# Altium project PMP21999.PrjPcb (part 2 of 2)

## Sheet PowerStage.SchDoc
size 431 x 279 mm; Date: Not shown in title block; ApprovedBy: Not shown in title block; CheckedBy: Not shown in title block; Author: Not shown in title block; CompanyName: Not shown in title block; Engineer: Not shown in title block; Organization: Not shown in title block; Address1: Not shown in title block; Address2: Not shown in title block; Address3: Not shown in title block; Address4: Not shown in title block; DocumentNumber: 1; Revision: Use project parameter SCH_Rev; SheetNumber: 1; SheetTotal: 2; PageSetup: Record=PageOptions¦CenterHorizontal=True¦CenterVertical=True¦PrintScale=1.00¦XCorrection=1.00¦YCorrection=1.00¦PrintKind=0¦BorderSize=5000000¦LeftOffset=0¦BottomOffset=0¦Orientation=2¦PaperLength=1000¦PaperWidth=1000¦Scale=100¦PaperSource=15¦PrintQuality=600¦MediaType=1¦DitherType=10¦PaperKind=Letter¦PrintScaleMode=1
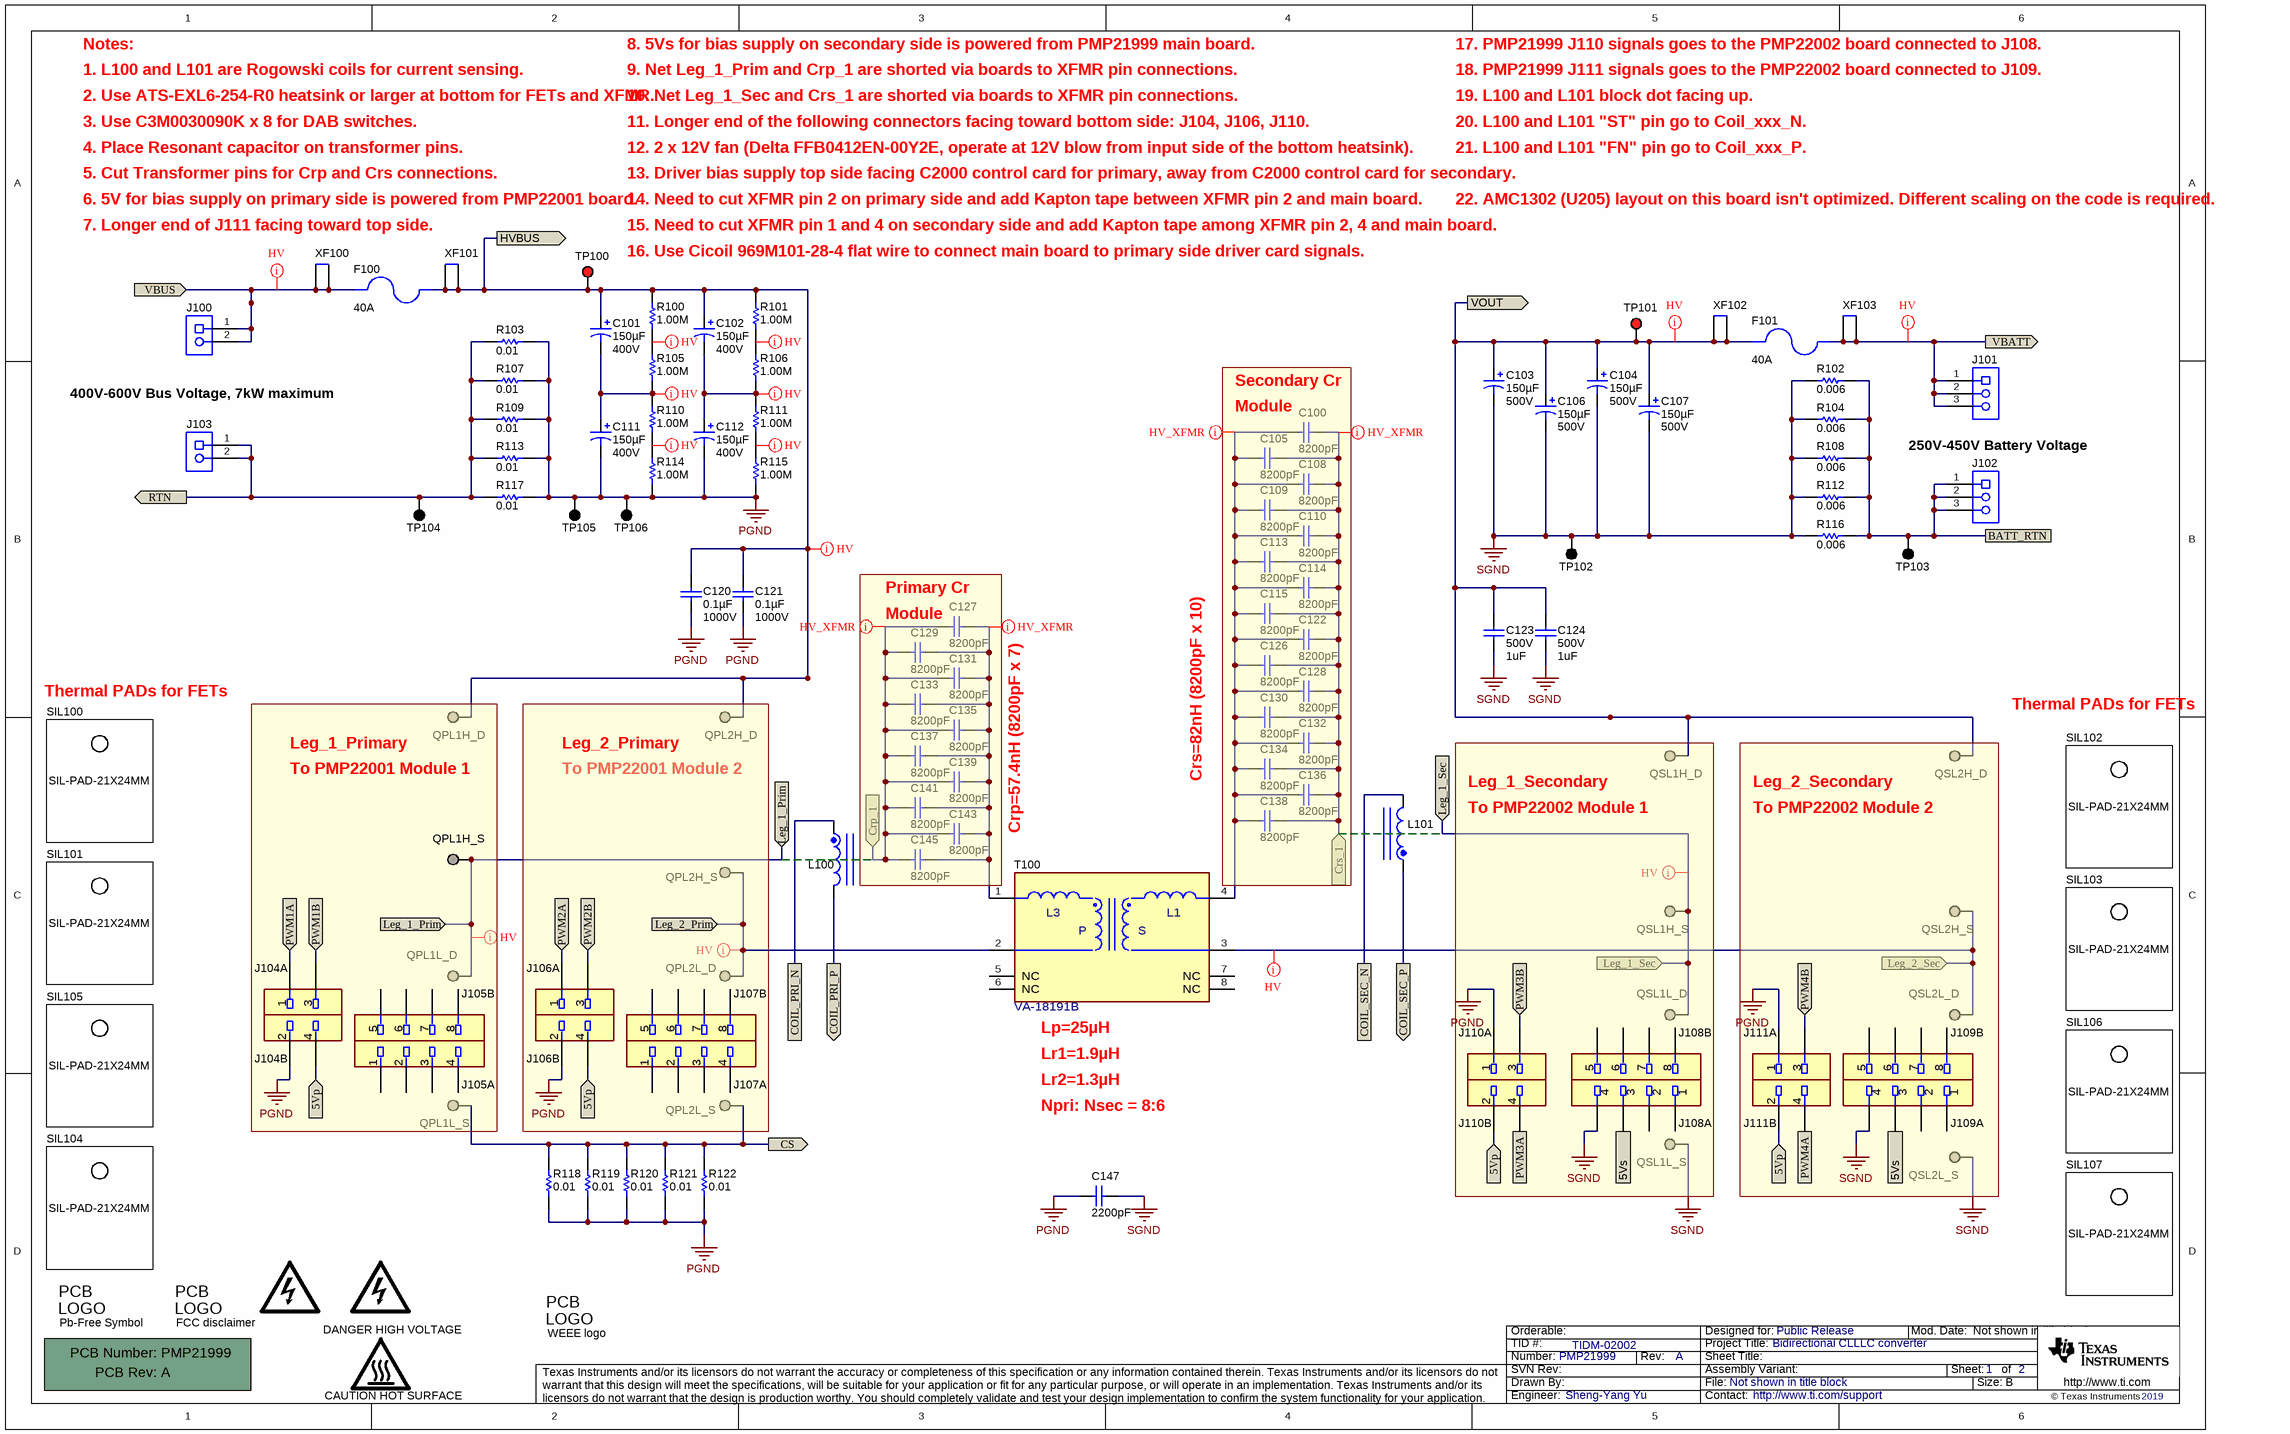
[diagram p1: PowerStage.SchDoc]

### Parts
!PCB100  Printed Circuit Board  (value not drawn)  (mechanical)
C100  ValueDisplayed: 8200pF  [1206_190]
C101  ValueDisplayed: 150µF  Value2: 400V  [FC_1600x4000]  (hidden comment: 400BXW150MEFC16X45)
C102  ValueDisplayed: 150µF  Value2: 400V  [FC_1600x4000]  (hidden comment: 400BXW150MEFC16X45)
C103  ValueDisplayed: 150µF  Value2: 500V  [Nichicon_2200x4500_Snap]  (hidden comment: 500MXG150MEFCSN22X55)
C104  ValueDisplayed: 150µF  Value2: 500V  [Nichicon_2200x4500_Snap]  (hidden comment: 500MXG150MEFCSN22X55)
C105  ValueDisplayed: 8200pF  [1206_190]
C106  ValueDisplayed: 150µF  Value2: 500V  [Nichicon_2200x4500_Snap]  (hidden comment: 500MXG150MEFCSN22X55)
C107  ValueDisplayed: 150µF  Value2: 500V  [Nichicon_2200x4500_Snap]  (hidden comment: 500MXG150MEFCSN22X55)
C108  ValueDisplayed: 8200pF  [1206_190]
C109  ValueDisplayed: 8200pF  [1206_190]
C110  ValueDisplayed: 8200pF  [1206_190]
C111  ValueDisplayed: 150µF  Value2: 400V  [FC_1600x4000]  (hidden comment: 400BXW150MEFC16X45)
C112  ValueDisplayed: 150µF  Value2: 400V  [FC_1600x4000]  (hidden comment: 400BXW150MEFC16X45)
C113  ValueDisplayed: 8200pF  [1206_190]
C114  ValueDisplayed: 8200pF  [1206_190]
C115  ValueDisplayed: 8200pF  [1206_190]
C120  ValueDisplayed: 0.1µF  Value2: 1000V  [1812_254]  (hidden comment: 1812Y1K00104KXT)
C121  ValueDisplayed: 0.1µF  Value2: 1000V  [1812_254]  (hidden comment: 1812Y1K00104KXT)
C122  ValueDisplayed: 8200pF  [1206_190]
C123  VDC_V: 500V  ValueDisplayed: 1uF  [B58031I_1084x785x450]  (hidden comment: B58031I5105M002)
C124  VDC_V: 500V  ValueDisplayed: 1uF  [B58031I_1084x785x450]  (hidden comment: B58031I5105M002)
C126  ValueDisplayed: 8200pF  [1206_190]
C127  ValueDisplayed: 8200pF  [1206_190]
C128  ValueDisplayed: 8200pF  [1206_190]
C129  ValueDisplayed: 8200pF  [1206_190]
C130  ValueDisplayed: 8200pF  [1206_190]
C131  ValueDisplayed: 8200pF  [1206_190]
C132  ValueDisplayed: 8200pF  [1206_190]
C133  ValueDisplayed: 8200pF  [1206_190]
C134  ValueDisplayed: 8200pF  [1206_190]
C135  ValueDisplayed: 8200pF  [1206_190]
C136  ValueDisplayed: 8200pF  [1206_190]
C137  ValueDisplayed: 8200pF  [1206_190]
C138  ValueDisplayed: 8200pF  [1206_190]
C139  ValueDisplayed: 8200pF  [1206_190]
C141  ValueDisplayed: 8200pF  [1206_190]
C143  ValueDisplayed: 8200pF  [1206_190]
C145  ValueDisplayed: 8200pF  [1206_190]
C147  ValueDisplayed: 2200pF  [CAPRD1000W60D900H1200]  (hidden comment: DE1E3KX222MA4BL01)
F100  Irating_A: 40A  (hidden comment: SC-40)  (mechanical)
F101  Irating_A: 40A  (hidden comment: SC-40)  (mechanical)
J100  282856-2  [TE_282856-2]  (value not drawn)
J101  282856-3  [TE_282856-3]  (value not drawn)
J102  282856-3  [TE_282856-3]  (value not drawn)
J103  282856-2  [TE_282856-2]  (value not drawn)
J104  MTMM-102-09-G-D-315  [FP-MTMM-102-09-G-D-315_HDR4-MFG]  (value not drawn)  (parts A,B of 2)
J105  MTMM-104-09-G-D-320  [FP-MTMM-104-09-G-D-320_HDR8-MFG]  (value not drawn)  (parts A,B of 2)
J106  MTMM-102-09-G-D-315  [FP-MTMM-102-09-G-D-315_HDR4-MFG]  (value not drawn)  (parts A,B of 2)
J107  MTMM-104-09-G-D-320  [FP-MTMM-104-09-G-D-320_HDR8-MFG]  (value not drawn)  (parts A,B of 2)
J108  MTMM-104-09-G-D-320  [FP-MTMM-104-09-G-D-320_HDR8-MFG]  (value not drawn)  (parts A,B of 2)
J109  MTMM-104-09-G-D-320  [FP-MTMM-104-09-G-D-320_HDR8-MFG]  (value not drawn)  (parts A,B of 2)
J110  MTMM-102-09-G-D-315  [FP-MTMM-102-09-G-D-315_HDR4-MFG]  (value not drawn)  (parts A,B of 2)
J111  MTMM-102-09-G-D-315  [FP-MTMM-102-09-G-D-315_HDR4-MFG]  (value not drawn)  (parts A,B of 2)
L100  RLTI-1310  [RLTI-1310]  (value not drawn)
L101  RLTI-1310  [RLTI-1310]  (value not drawn)
LOGO100  CAUTION HOT SURFACE  [IEC_HotSurface_Medium]  (no BOM)
Logo101  Pb-Free Symbol  [Pb-Free_Overlay_Medium]  (no BOM)
Logo102  FCC disclaimer  [FCC_disclaimer]  (no BOM)
Logo103  WEEE logo  [WEEE_Minimum]  (no BOM)
LOGO104  DANGER HIGH VOLTAGE  [IEC_HighVoltage_Medium]  (value not drawn)  (no BOM)
LOGO105  DANGER HIGH VOLTAGE  [IEC_HighVoltage_Medium]  (no BOM)
QPL1H_D  Suggest using a net name here  [Mill-Max_0312-0-15-15-34-27-10-0]  (value not drawn)
QPL1H_S  Suggest using a net name here  [Mill-Max_0312-0-15-15-34-27-10-0]  (value not drawn)
QPL1L_D  Suggest using a net name here  [Mill-Max_0312-0-15-15-34-27-10-0]  (value not drawn)
QPL1L_S  Suggest using a net name here  [Mill-Max_0312-0-15-15-34-27-10-0]  (value not drawn)
QPL2H_D  Suggest using a net name here  [Mill-Max_0312-0-15-15-34-27-10-0]  (value not drawn)
QPL2H_S  Suggest using a net name here  [Mill-Max_0312-0-15-15-34-27-10-0]  (value not drawn)
QPL2L_D  Suggest using a net name here  [Mill-Max_0312-0-15-15-34-27-10-0]  (value not drawn)
QPL2L_S  Suggest using a net name here  [Mill-Max_0312-0-15-15-34-27-10-0]  (value not drawn)
QSL1H_D  Suggest using a net name here  [Mill-Max_0312-0-15-15-34-27-10-0]  (value not drawn)
QSL1H_S  Suggest using a net name here  [Mill-Max_0312-0-15-15-34-27-10-0]  (value not drawn)
QSL1L_D  Suggest using a net name here  [Mill-Max_0312-0-15-15-34-27-10-0]  (value not drawn)
QSL1L_S  Suggest using a net name here  [Mill-Max_0312-0-15-15-34-27-10-0]  (value not drawn)
QSL2H_D  Suggest using a net name here  [Mill-Max_0312-0-15-15-34-27-10-0]  (value not drawn)
QSL2H_S  Suggest using a net name here  [Mill-Max_0312-0-15-15-34-27-10-0]  (value not drawn)
QSL2L_D  Suggest using a net name here  [Mill-Max_0312-0-15-15-34-27-10-0]  (value not drawn)
QSL2L_S  Suggest using a net name here  [Mill-Max_0312-0-15-15-34-27-10-0]  (value not drawn)
R100  ValueDisplayed: 1.00M  [1206]  (hidden comment: CRCW12061M00FKEA)
R101  ValueDisplayed: 1.00M  [1206]  (hidden comment: CRCW12061M00FKEA)
R102  ValueDisplayed: 0.006  [CSNL1206]  (hidden comment: PMR18EZPFU6L00)
R103  ValueDisplayed: 0.01  [1206]  (hidden comment: WSLP1206R0100FEA)
R104  ValueDisplayed: 0.006  [CSNL1206]  (hidden comment: PMR18EZPFU6L00)
R105  ValueDisplayed: 1.00M  [1206]  (hidden comment: CRCW12061M00FKEA)
R106  ValueDisplayed: 1.00M  [1206]  (hidden comment: CRCW12061M00FKEA)
R107  ValueDisplayed: 0.01  [1206]  (hidden comment: WSLP1206R0100FEA)
R108  ValueDisplayed: 0.006  [CSNL1206]  (hidden comment: PMR18EZPFU6L00)
R109  ValueDisplayed: 0.01  [1206]  (hidden comment: WSLP1206R0100FEA)
R110  ValueDisplayed: 1.00M  [1206]  (hidden comment: CRCW12061M00FKEA)
R111  ValueDisplayed: 1.00M  [1206]  (hidden comment: CRCW12061M00FKEA)
R112  ValueDisplayed: 0.006  [CSNL1206]  (hidden comment: PMR18EZPFU6L00)
R113  ValueDisplayed: 0.01  [1206]  (hidden comment: WSLP1206R0100FEA)
R114  ValueDisplayed: 1.00M  [1206]  (hidden comment: CRCW12061M00FKEA)
R115  ValueDisplayed: 1.00M  [1206]  (hidden comment: CRCW12061M00FKEA)
R116  ValueDisplayed: 0.006  [CSNL1206]  (hidden comment: PMR18EZPFU6L00)
R117  ValueDisplayed: 0.01  [1206]  (hidden comment: WSLP1206R0100FEA)
R118  ValueDisplayed: 0.01  [1206]  (hidden comment: WSLP1206R0100FEA)
R119  ValueDisplayed: 0.01  [1206]  (hidden comment: WSLP1206R0100FEA)
R120  ValueDisplayed: 0.01  [1206]  (hidden comment: WSLP1206R0100FEA)
R121  ValueDisplayed: 0.01  [1206]  (hidden comment: WSLP1206R0100FEA)
R122  ValueDisplayed: 0.01  [1206]  (hidden comment: WSLP1206R0100FEA)
SIL100  SP900S-0.009-00-114  [SIL-PAD_24X21MM]  (value not drawn)
SIL101  SP900S-0.009-00-114  [SIL-PAD_24X21MM]  (value not drawn)
SIL102  SP900S-0.009-00-114  [SIL-PAD_24X21MM]  (value not drawn)
SIL103  SP900S-0.009-00-114  [SIL-PAD_24X21MM]  (value not drawn)
SIL104  SP900S-0.009-00-114  [SIL-PAD_24X21MM]  (value not drawn)
SIL105  SP900S-0.009-00-114  [SIL-PAD_24X21MM]  (value not drawn)
SIL106  SP900S-0.009-00-114  [SIL-PAD_24X21MM]  (value not drawn)
SIL107  SP900S-0.009-00-114  [SIL-PAD_24X21MM]  (value not drawn)
T100  VA-18191B  [FP-VA-18191B_XFMR_PTH_8-MFG]
TP100  5000  [Keystone5000]  (value not drawn)
TP101  5000  [Keystone5000]  (value not drawn)
TP102  5001  [Keystone5001]  (value not drawn)
TP103  5001  [Keystone5001]  (value not drawn)
TP104  5001  [Keystone5001]  (value not drawn)
TP105  5001  [Keystone5001]  (value not drawn)
TP106  5001  [Keystone5001]  (value not drawn)
XF100  1A3400-10  [Eaton_1A3400-10]  (value not drawn)
XF101  1A3400-10  [Eaton_1A3400-10]  (value not drawn)
XF102  1A3400-10  [Eaton_1A3400-10]  (value not drawn)
XF103  1A3400-10  [Eaton_1A3400-10]  (value not drawn)

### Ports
5Vp (in), 5Vs (in), BATT_RTN, COIL_PRI_N, COIL_PRI_P (out), COIL_SEC_N, COIL_SEC_P (out), Crp_1 (in), Crs_1 (in), CS (out), HVBUS (out), Leg_1_Prim (in), Leg_1_Sec (in), Leg_2_Prim (in), Leg_2_Sec (in), PWM1A (in), PWM1B (in), PWM2A (in), PWM2B (in), PWM3A (in), PWM3B (in), PWM4A (in), PWM4B (in), RTN (out), VBATT (out), VBUS (in), VOUT (out)

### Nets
PGND: C111.2(-) C112.2(-) C120.2 C121.2 C147.2 J104.2 J106.2 J110.1 J111.1 R103.1 R107.1 R109.1 R113.1 R114.1 R115.1 R117.1 R118.1 R119.1 R120.1 R121.1 R122.1 TP105.1 TP106.1
SGND: C103.2(-) C104.2(-) C106.2(-) C107.2(-) C123.2 C124.2 C147.1 J108.4 J109.4 QSL1L_S.1 QSL2L_S.1 R102.2 R104.2 R108.2 R112.2 R116.2 TP102.1
5Vp: J104.4 J106.4 J110.2 J111.2 ; port 5Vp
5Vs: J108.3 J109.3 ; port 5Vs
BATT_RTN: J102.1 J102.2 J102.3 R102.1 R104.1 R108.1 R112.1 R116.1 TP103.1 ; port BATT_RTN
COIL_PRI_N: L100.1 ; port COIL_PRI_N
COIL_PRI_P: L100.2 ; port COIL_PRI_P
COIL_SEC_N: L101.2 ; port COIL_SEC_N
COIL_SEC_P: L101.1 ; port COIL_SEC_P
Crp_1: C127.2 C129.2 C131.2 C133.2 C135.2 C137.2 C139.2 C141.2 C143.2 C145.2 ; port Crp_1
Crs_1: C100.1 C105.1 C108.1 C109.1 C110.1 C113.1 C114.1 C115.1 C122.1 C126.1 C128.1 C130.1 C132.1 C134.1 C136.1 C138.1 ; port Crs_1
CS: QPL1L_S.1 QPL2L_S.1 R118.2 R119.2 R120.2 R121.2 R122.2 ; port CS
HVBUS: C101.1(+) C102.1(+) C120.1 C121.1 QPL1H_D.1 QPL2H_D.1 R100.2 R101.2 TP100.1 XF101.1 XF101.2 ; port HVBUS
Leg_1_Prim: QPL1H_S.1 QPL1L_D.1 ; port Leg_1_Prim
Leg_1_Sec: QSL1H_S.1 QSL1L_D.1 ; port Leg_1_Sec
Leg_2_Prim: QPL2H_S.1 QPL2L_D.1 T100.2 ; port Leg_2_Prim
Leg_2_Sec: QSL2H_S.1 QSL2L_D.1 T100.3 ; port Leg_2_Sec
PWM1A: J104.1 ; port PWM1A
PWM1B: J104.3 ; port PWM1B
PWM2A: J106.1 ; port PWM2A
PWM2B: J106.3 ; port PWM2B
PWM3A: J110.4 ; port PWM3A
PWM3B: J110.3 ; port PWM3B
PWM4A: J111.4 ; port PWM4A
PWM4B: J111.3 ; port PWM4B
RTN: J103.1 J103.2 R103.2 R107.2 R109.2 R113.2 R117.2 TP104.1 ; port RTN
VBATT: J101.1 J101.2 J101.3 XF103.1 XF103.2 ; port VBATT
VBUS: J100.1 J100.2 XF100.1 XF100.2 ; port VBUS
VOUT: C103.1(+) C104.1(+) C106.1(+) C107.1(+) C123.1 C124.1 QSL1H_D.1 QSL2H_D.1 TP101.1 XF102.1 XF102.2 ; port VOUT
NetC100_2: C100.2 C105.2 C108.2 C109.2 C110.2 C113.2 C114.2 C115.2 C122.2 C126.2 C128.2 C130.2 C132.2 C134.2 C136.2 C138.2 T100.4
NetC101_2: C101.2(-) C111.1(+) R105.1 R110.2
NetC102_2: C102.2(-) C112.1(+) R106.1 R111.2
NetC127_1: C127.1 C129.1 C131.1 C133.1 C135.1 C137.1 C139.1 C141.1 C143.1 C145.1 T100.1
NetR100_1: R100.1 R105.2
NetR101_1: R101.1 R106.2
NetR110_1: R110.1 R114.2
NetR111_1: R111.1 R115.2

Not connected (* = marked no-connect by the designer): J105 1 2 3 4 5 6 7 8; J107 1 2 3 4 5 6 7 8; J108 1 2 5 6 7 8; J109 1 2 5 6 7 8; T100 5(NC) 6(NC) 7(NC) 8(NC)

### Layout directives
net class HV: HVBUS, Leg_1_Prim, Leg_1_Sec, Leg_2_Prim, Leg_2_Sec, NetC101_2, NetC102_2, NetR100_1, NetR101_1, NetR110_1, NetR111_1, VBATT, VBUS, VOUT
net class HV_XFMR: Crp_1, Crs_1, NetC100_2, NetC127_1

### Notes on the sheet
- Notes:
- 1. L100 and L101 are Rogowski coils for current sensing.
- 2. Use ATS-EXL6-254-R0 heatsink or larger at bottom for FETs and XFMR.
- 9. Net Leg_1_Prim and Crp_1 are shorted via boards to XFMR pin connections.
- 10. Net Leg_1_Sec and Crs_1 are shorted via boards to XFMR pin connections.
- 8. 5Vs for bias supply on secondary side is powered from PMP21999 main board.
- 17. PMP21999 J110 signals goes to the PMP22002 board connected to J108.
- 18. PMP21999 J111 signals goes to the PMP22002 board connected to J109.
- 19. L100 and L101 block dot facing up.
- 3. Use C3M0030090K x 8 for DAB switches.
- 4. Place Resonant capacitor on transformer pins.
- 12. 2 x 12V fan (Delta FFB0412EN-00Y2E, operate at 12V blow from input side of the bottom heatsink).
- 11. Longer end of the following connectors facing toward bottom side: J104, J106, J110.
- 20. L100 and L101 "ST" pin go to Coil_xxx_N.
- 21. L100 and L101 "FN" pin go to Coil_xxx_P.
- 5. Cut Transformer pins for Crp and Crs connections.
- 6. 5V for bias supply on primary side is powered from PMP22001 board.
- 7. Longer end of J111 facing toward top side.
- 13. Driver bias supply top side facing C2000 control card for primary, away from C2000 control card for secondary.
- 14. Need to cut XFMR pin 2 on primary side and add Kapton tape between XFMR pin 2 and main board.
- 15. Need to cut XFMR pin 1 and 4 on secondary side and add Kapton tape among XFMR pin 2, 4 and main board.
- 22. AMC1302 (U205) layout on this board isn't optimized. Different scaling on the code is required.
- 16. Use Cicoil 969M101-28-4 flat wire to connect main board to primary side driver card signals.
- 400V-600V Bus Voltage, 7kW maximum
- (near C100) Secondary Cr
- (near C100) Module
- 250V-450V Battery Voltage
- (near C127) Primary Cr
- (near C127) Module
- Thermal PADs for FETs
- Leg_1_Primary
- Leg_2_Primary
- (near QPL1H_D) To PMP22001 Module 1
- (near QPL2H_D) To PMP22001 Module 2
- Crs=82nH (8200pF x 10)
- To PMP22002 Module 1
- Leg_1_Secondary
- To PMP22002 Module 2
- Leg_2_Secondary
- Crp=57.4nH (8200pF x 7)
- (near T100) Lp=25µH
- Lr1=1.9µH
- Npri: Nsec = 8:6
- Lr2=1.3µH

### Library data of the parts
!PCB100 = CMP-0003618-2: Manufacturer: Any; PartNumber: PMP21999
C100 C105 C108-C110 C113-C115 C122 C126-C139 C141 C143 C145 = CMP-0008795-2: CAP CER 8200PF 630V NP0 1206; Manufacturer: TDK; PartNumber: CGA5L4NP02J822J160AA; TaMin_C: -55°C; Polarized: N; TempCo: C0G; SizeAreaWB_mm2: 10.92; Value1: Unknown; U/M: EA; TaMax_C: 125°C; Tolerance_%: 5%; SizeZ_mm: 1.9; SizeX_mm: 3.2; SizeY_mm: 1.6; Cap_Case: 1206; SizeArea_mm2: 5.12; CompType: Capacitor; AEC Qualified: Y; Cap_F: 100nF; AEC Grade: 1; AEC Category: Q200
C101 C102 C111 C112 = EEU-FC2A471: CAP ALUM 150UF 20% 400V RADIAL; Manufacturer: Rubycon; Polarized: Y; CompType: Capacitor; U/M: EA; Tolerance_%: 20; VDC_V: 400; ESR_ohm: 0.047; IRMS_A: 1.92; TaMin_C: -55; TaMax_C: 105; Cap_Case: 16x40mm; SizeAreaWB_mm2: 324; SizeArea_mm2: 256; SizeX_mm: 16; SizeZ_mm: 42; AEC Category: Q200; AEC Grade: 2; Green_Lifecycle: Active; Green_REACh: Passed
C103 C104 C106 C107 = LLS2G221MELZ: CAP ALUM 150UF 20% 500V SNAP; Manufacturer: Rubycon; Polarized: Y; CompType: Capacitor; U/M: EA; Cap_F: 0.00022; Tolerance_%: 20; VDC_V: 500; IRMS_A: 1.58; Cap_Case: 22x45mm; SizeAreaWB_mm2: 576; SizeArea_mm2: 484; SizeX_mm: 22; SizeZ_mm: 47; AEC Category: Q200; AEC Qualified: N
C120 = C1812W104KDRACTU: CAP, CERM, 0.1 µF, 1000 V,+/- 10%, X7R, 1812; Manufacturer: Knowles Syfer; Polarized: N; CompType: Capacitor; Value: 0.1uF; U/M: EA; Cap_F: 0.0000001; Tolerance_%: 10; VDC_V: 1000; TaMin_C: -55; TaMax_C: 125; Cap_Case: 1812; SizeArea_mm2: 14.4; SizeAreaWB_mm2: 23.1; SizeX_mm: 4.5; SizeY_mm: 3.2; SizeZ_mm: 2.54; AEC Category: Q200; Green_Lifecycle: Active; Green_REACh: Passed
C121 = C1812W104KDRACTU: CAP CER 0.1UF 1KV X7R 1812; Manufacturer: Knowles Syfer; Polarized: N; CompType: Capacitor; U/M: EA; Cap_F: 0.0000001; Tolerance_%: 10; VDC_V: 1000; TaMin_C: -55; TaMax_C: 125; Cap_Case: 1812; SizeArea_mm2: 14.4; SizeAreaWB_mm2: 23.1; SizeX_mm: 4.5; SizeY_mm: 3.2; SizeZ_mm: 2.54; AEC Category: Q200; Green_Lifecycle: Active; Green_REACh: Passed
C123 C124 = CMP-0009311-2: CAP, CERM, 1 uF, 500 V, +/- 20%, B58031, AEC-Q200 Grade 0, 6.84x7.85mm; Manufacturer: TDK; PartNumber: B58031I5105M062; TaMin_C: -40°C; Polarized: N; SizeAreaWB_mm2: 126.474; Value1: Unknown; U/M: EA; Value: 1uF; TaMax_C: 150°C; SizeZ_mm: 4.5; SizeX_mm: 10.84; SizeY_mm: 7.85; Cap_Case: 10.84x7.85x4.5mm; SizeArea_mm2: 85.094; CompType: Capacitor; AEC Qualified: Y; Cap_F: 1µF; IRMS_A: 7.5A; AEC Grade: 0; AEC Category: Q200
C147 = DE1E3KX222MA4BL01: CAP, CERM, 2200 pF, 250 V, +/- 20%, E, Cap, 7x12x9 mm; Manufacturer: MuRata; Polarized: N; CompType: Capacitor; Value: 2200pF; U/M: EA; Cap_F: 0.0000000022; Tolerance_%: 20; Value1: Unknown; VDC_V: 250; Value2: 250V; TaMin_C: -25; TaMax_C: 85
F100 F101 = CMP-0082087-1: Fuse, 40 A, 480 VAC, 300 VDC, Holder; Manufacturer: Eaton; Fuse Speed: Slow; Fuse Technology: Cartridge; VAC_V: 480V; Interrupt_AC: 100kA; VDC_V: 300V; Interrupt_DC: 10kA
J100 J103 = CMP-0054978-1: Therminal Block, 5 mm, 2-pole, Tin, TH; Manufacturer: On Shore Technology Inc.; PartNumber: ED700/2; CT: TRUE; CompType: Terminal Block; CNHeader: FALSE
J101 J102 = CMP-0054983-1: Receptacle, 3x1, 5mm, R/A, TH; Manufacturer: On Shore Technology Inc.; PartNumber: ED700/3; CNHeader: FALSE; Current_A: 24A; Gender: Female; Voltage_V: 300V; CompType: Terminal Block; Row_Count: 1; Pitch_mm: 5; ContactFinish: Tin; CT: TRUE; Cert_UL: Y
J104 J106 = CMP-0087195-1: Conn Unshrouded Header HDR 4 POS 2mm Solder ST Thru-Hole; Manufacturer: Samtec; ContactFinish: Gold,Nickel; Row_Count: 2; Symbol Name: SYM-MTMM-102-09-G-D-315
J105 J107-J109 = CMP-0087215-1: Conn Unshrouded Header HDR 8 POS 2mm Solder ST Thru-Hole; Manufacturer: Samtec; Row_Count: 2; ContactFinish: Gold,Nickel; Symbol Name: SYM-MTMM-104-09-G-D-320
J110 J111 = CMP-0087195-1: Conn Unshrouded Header HDR 4 POS 2mm Solder ST Thru-Hole; PartNumber: MTMM-102-04-G-D-148; Manufacturer: Samtec; ContactFinish: Gold,Nickel; Row_Count: 2; Symbol Name: SYM-MTMM-102-09-G-D-315
L100 L101 = CMP-0086080-1: Inductor, Toroid, 7 µH, 1.155 ohm, TH; Manufacturer: Renco Electronics; SizeZ_mm: 18.669; SizeAreaWB_mm2: 135.836668; SizeX_mm: 4.572; AEC Qualified: N; AEC Category: Q200; Ind_H: 7µH; DCR_ohm: 1.155; Value: 7uH; Value2: A; SizeArea_mm2: 85.354668
LOGO100 = IEC_HotSurface: IEC 61010-1 Hot Surface Warning; SymbolCreator: a0412235
Logo101 = CMP-0074839-1: SymbolCreator: a0412235; Library Reference: Logo
Logo102 = CMP-0074847-1: FCC_disclaimer; Library Reference: Logo
Logo103 = CMP-0074769-1
LOGO104 LOGO105 = IEC_HighVoltage: IEC 61010-1 High Voltage Warning; SymbolCreator: a0412235
QPL1H_D QPL1H_S QPL1L_D QPL1L_S QPL2H_D QPL2H_S QPL2L_D QPL2L_S QSL1H_D QSL1H_S QSL1L_D QSL1L_S QSL2H_D QSL2H_S QSL2L_D QSL2L_S = 0312-0-15-15-34-27-10-0: Pin Receptacle, .032-.046" .075" Dia, Gold, TH; Manufacturer: Mill-Max; Gender: Female
R100 R101 R105 R106 R110 R111 R114 R115 = CRCW12061M00FKEA: RES, 1.00 M, 1%, 0.25 W, 1206; Manufacturer: Vishay-Dale; CompType: Resistor; Value: 1.00Meg; Res_ohm: 1000000; Value_Code: 1M00; Tolerance_%: 1; Power_W: 0.25; Value2: 0.25W; VDC_V: 200; TempCo: 100 ppm/C; SizeArea_mm2: 5.12; SizeX_mm: 3.2; SizeY_mm: 1.6; SizeZ_mm: 1.35; EIA_Code: E96; U/M: EA; AEC Category: Q200; Green_Lifecycle: Active; Green_REACh: Passed
R102 R104 R108 R112 R116 = CSNL1206FT5L00: RES 0.006 OHM 1% 1W 1206; Manufacturer: Rohm Semiconductor; CompType: Resistor; Value: 0.006; Tolerance_%: 1; TempCo: 50 ppm/C; SizeArea_mm2: 5.12; SizeX_mm: 3.2; SizeY_mm: 1.6; SizeZ_mm: 0.9; EIA_Code: E96; U/M: EA; AEC Category: Q200; AEC Qualified: N
R103 R107 R109 R113 R117-R122 = CMP-0018570-2: RES, 0.01, 1%, 1 W, 1206; Manufacturer: Vishay-Dale; Power_W: 1W; TempCo: 75 ppm/C; Value_Code: R010; U/M: EA; Value: 0.01; EIA_Code: E96; SizeX_mm: 3.2; SizeY_mm: 1.6; SizeZ_mm: 1.35; SizeArea_mm2: 5.12; CompType: Resistor; AEC Category: Q200
SIL100-SIL107 = CMP-0003644-1: Silcon Thermal Pad; Manufacturer: Bergquist Company
T100 = CMP-0086457-1: LLC Transformer; Manufacturer: Cyntec; SizeZ_mm: 40.5mm; Symbol Name: SYM-VA-18191B; AEC Qualified: No; Ind_H: 25µH; Ns1toNp: 4:3
TP100 TP101 = 5000: Test Point, Miniature, Red, TH; Manufacturer: Keystone; CompType: Test Point Loop; ContactFinish: Silver; Green_Lifecycle: Active; Green_REACh: Passed
TP102-TP106 = 5001: Test Point, Miniature, Black, TH; Manufacturer: Keystone; CompType: Test Point Loop; ContactFinish: Silver; Green_Lifecycle: Active; Green_REACh: Passed
XF100-XF103 = CMP-0082116-2: FUSE CLIP CARTRIDGE 30A PCB; PartNumber: BK/1A3400-10; Manufacturer: Eaton; CompType: Fuse Holder

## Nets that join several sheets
PGND: Controller (69 pins), PowerStage (23 pins)
SGND: Controller (9 pins), PowerStage (17 pins)
5Vp: Controller (22 pins), PowerStage (J104.4 J106.4 J110.2 J111.2)
5Vs: Controller (6 pins), PowerStage (J108.3 J109.3)
BATT_RTN: Controller (R232.1), PowerStage (9 pins)
COIL_PRI_N: Controller (5 pins), PowerStage (L100.1)
COIL_PRI_P: Controller (R248.1), PowerStage (L100.2)
COIL_SEC_N: Controller (5 pins), PowerStage (L101.2)
COIL_SEC_P: Controller (R230.1), PowerStage (L101.1)
CS: Controller (R205.2), PowerStage (7 pins)
HVBUS: Controller (R240.2), PowerStage (11 pins)
PWM1A: Controller (J200.49), PowerStage (J104.1)
PWM1B: Controller (J200.51), PowerStage (J104.3)
PWM2A: Controller (J200.53), PowerStage (J106.1)
PWM2B: Controller (J200.55), PowerStage (J106.3)
PWM3A: Controller (J200.50), PowerStage (J110.4)
PWM3B: Controller (J200.52), PowerStage (J110.3)
PWM4A: Controller (J200.54), PowerStage (J111.4)
PWM4B: Controller (J200.56), PowerStage (J111.3)
RTN: Controller (R202.1), PowerStage (8 pins)
VBATT: Controller (J203.1 R241.2), PowerStage (5 pins)

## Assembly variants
001: not fitted C100 C105 C108 C109 C110 C113 C141 C143 C145 C210 C220 C221 C228 C229 C230 C232 C233 C242 C243 C244 C246 J203 J204 R203 R213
